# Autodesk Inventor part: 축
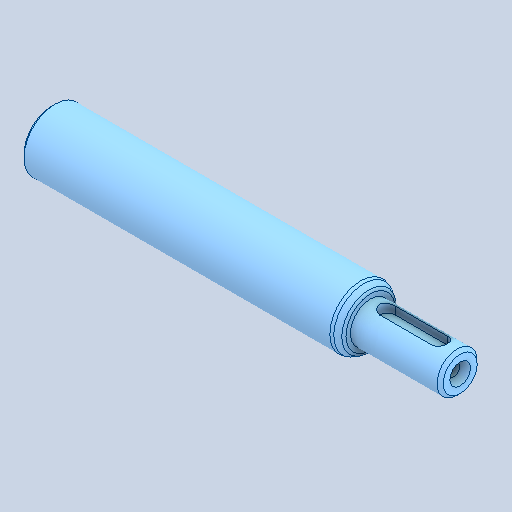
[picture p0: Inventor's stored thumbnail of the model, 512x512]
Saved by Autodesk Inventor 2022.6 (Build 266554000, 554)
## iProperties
Created: 2024-09
Part Number: 축
Material: 강철, 탄소
Document SubType Name: Modeling
Designer: Class 001
Density: 7.85 g/cm^3
Appearance: 기본값
Author: jhkim
Sending System: Autodesk Inventor 2025
Preprocessor: ST-DEVELOPER v20
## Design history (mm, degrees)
feature "솔리드1"
node "솔리드2"
